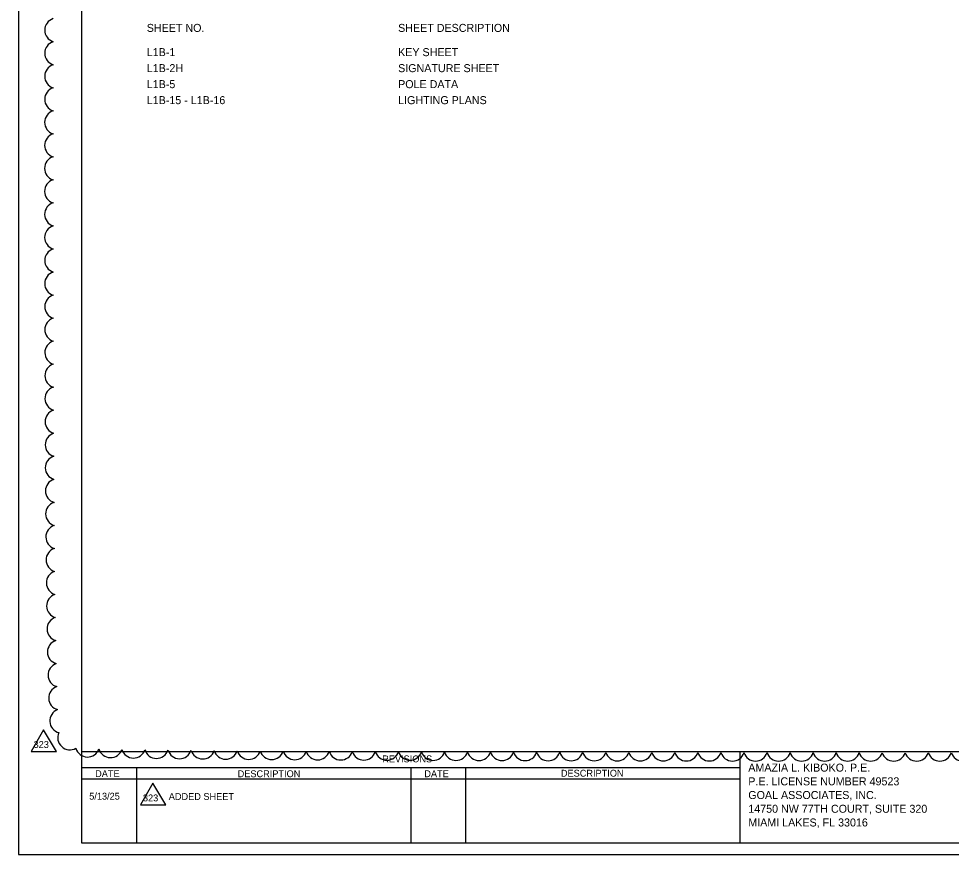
# Model space of a CAD drawing. Extents: x -811.2 to -755.6, y -2295.2 to -2235.1.
# Drawn here: x -783.91 to -775.75, y -2282.95 to -2275.63 of the extents above; entities that cross this region are included whole.
import ezdxf

# ---------------------------------------------------------------- set-up
doc = ezdxf.new("R2010")
doc.units = 0
for name, color, linetype in [('Cloud_dp', 7, 'Continuous'), ('PlotBorder_dp', 7, 'Continuous'), ('SheetBorder_dp', 7, 'Continuous'), ('SheetLines_dp', 7, 'Continuous'), ('TextMinor', 7, 'Continuous'), ('TextMisc', 7, 'Continuous'), ('TextNotes', 7, 'Continuous'), ('TextTitle', 7, 'Continuous')]:
    doc.layers.add(name, color=color, linetype=linetype)

msp = doc.modelspace()

# ---------------------------------------------------------------- linework, layer by layer
at = {"layer": 'Cloud_dp'}
for points in [[(-783.6889, -2281.8566), (-783.7966, -2282.0447), (-783.576, -2282.0447)], [(-782.7321, -2282.3241), (-782.8398, -2282.5122), (-782.6192, -2282.5122)]]:
    msp.add_lwpolyline(points, close=True, dxfattribs=at)
for centre, start, end in [((-783.5726, -2275.7344), 107.45847, 252.45847), ((-783.5727, -2275.9359), 107.46563, 252.46563), ((-783.5728, -2276.1375), 107.47218, 252.47218), ((-783.5729, -2276.339), 107.47822, 252.47822), ((-783.573, -2276.5406), 107.4838, 252.4838), ((-783.573, -2276.7421), 107.48899, 252.48899), ((-783.5731, -2276.9436), 107.49382, 252.49382), ((-783.5731, -2277.1452), 107.49843, 252.49843), ((-783.573, -2277.3467), 107.51148, 252.51148), ((-783.573, -2277.5483), 107.53101, 252.53101), ((-783.5728, -2277.7498), 107.55191, 252.55191), ((-783.5726, -2277.9513), 107.57435, 252.57435), ((-783.5723, -2278.1529), 107.59852, 252.59852), ((-783.5719, -2278.3544), 107.62468, 252.62468), ((-783.5714, -2278.5559), 107.65309, 252.65309), ((-783.5708, -2278.7575), 107.68411, 252.68411), ((-783.5701, -2278.959), 107.71817, 252.71817), ((-783.5693, -2279.1605), 107.75578, 252.75578), ((-783.5683, -2279.3621), 107.79762, 252.79762), ((-783.5672, -2279.5636), 107.84454, 252.84454), ((-783.5659, -2279.7651), 107.89767, 252.89767), ((-783.5644, -2279.9666), 107.95851, 252.95851), ((-783.5626, -2280.1681), 108.02912, 253.02912), ((-783.5606, -2280.3696), 108.11243, 253.11243), ((-783.5583, -2280.5711), 108.21279, 253.21279), ((-783.5556, -2280.7725), 108.33694, 253.33694), ((-783.5523, -2280.974), 108.49611, 253.49611), ((-783.5485, -2281.1754), 108.71068, 253.71068), ((-783.5437, -2281.3767), 109.02298, 254.02298), ((-783.5374, -2281.5778), 109.54201, 254.54201), ((-783.5282, -2281.7785), 110.71007, 255.71007), ((-783.4585, -2281.9255), 155.06518, 300.06518), ((-783.3038, -2281.9884), 195.62937, 340.62937), ((-783.1027, -2281.9939), 196.26473, 341.26473), ((-782.9013, -2281.9977), 196.54985, 341.54985), ((-782.6999, -2282.0008), 196.72204, 341.72204), ((-782.4984, -2282.0033), 196.84059, 341.84059), ((-782.2969, -2282.0055), 196.92865, 341.92865), ((-782.0954, -2282.0073), 196.99739, 341.99739), ((-781.8939, -2282.009), 197.053, 342.053), ((-781.6924, -2282.0105), 197.09919, 342.09919), ((-781.4909, -2282.0118), 197.13834, 342.13834), ((-781.2893, -2282.0131), 197.17209, 342.17209), ((-781.0878, -2282.0142), 197.20158, 342.20158), ((-780.8863, -2282.0152), 197.22762, 342.22762), ((-780.6847, -2282.0161), 197.25085, 342.25085), ((-780.4832, -2282.0169), 197.27174, 342.27174), ((-780.2817, -2282.0177), 197.29065, 342.29065), ((-780.0801, -2282.0184), 197.30788, 342.30788), ((-779.8786, -2282.019), 197.32367, 342.32367), ((-779.6771, -2282.0196), 197.3382, 342.3382), ((-779.4755, -2282.0202), 197.35163, 342.35163), ((-779.274, -2282.0207), 197.3641, 342.3641), ((-779.0724, -2282.0211), 197.37571, 342.37571), ((-778.8709, -2282.0216), 197.38657, 342.38657), ((-778.6693, -2282.0219), 197.39674, 342.39674), ((-778.4678, -2282.0223), 197.40629, 342.40629), ((-778.2663, -2282.0226), 197.4153, 342.4153), ((-778.0647, -2282.0229), 197.4238, 342.4238), ((-777.8632, -2282.0231), 197.43184, 342.43184), ((-777.6616, -2282.0234), 197.43947, 342.43947), ((-777.4601, -2282.0236), 197.44671, 342.44671), ((-777.2585, -2282.0237), 197.4536, 342.4536), ((-777.057, -2282.0239), 197.46017, 342.46017), ((-776.8554, -2282.024), 197.46644, 342.46644), ((-776.6539, -2282.0241), 197.47243, 342.47243), ((-776.4524, -2282.0242), 197.47816, 342.47816), ((-776.2508, -2282.0243), 197.48365, 342.48365), ((-776.0493, -2282.0243), 197.48892, 342.48892), ((-775.8477, -2282.0244), 197.49398, 342.49398), ((-775.6462, -2282.0244), 197.49888, 342.49888)]:
    msp.add_arc(centre, 0.1057, start, end, dxfattribs=at)
at = {"layer": 'PlotBorder_dp'}
msp.add_lwpolyline([(-783.9062, -2282.9457), (-767.4062, -2282.9457), (-767.4062, -2272.3457), (-783.9062, -2272.3457)], close=True, dxfattribs=at)
at = {"layer": 'SheetBorder_dp'}
for p, q in [((-783.3562, -2272.4457), (-783.3562, -2282.8457)), ((-783.3562, -2282.0457), (-767.9562, -2282.0457)), ((-783.3562, -2282.8457), (-767.9562, -2282.8457))]:
    msp.add_line(p, q, dxfattribs=at)
at = {"layer": 'SheetLines_dp'}
for p, q in [((-777.5962, -2282.0457), (-777.5962, -2282.8457)), ((-783.3562, -2282.1857), (-777.5962, -2282.1857)), ((-782.8762, -2282.1857), (-782.8762, -2282.8457)), ((-780.4762, -2282.1857), (-780.4762, -2282.8457)), ((-779.9962, -2282.1857), (-779.9962, -2282.8457)), ((-783.3562, -2282.2857), (-777.5962, -2282.2857))]:
    msp.add_line(p, q, dxfattribs=at)

# ---------------------------------------------------------------- texts
at = {"layer": 'Cloud_dp'}
for p in [(-783.7757, -2282.0146), (-782.8189, -2282.482)]:
    msp.add_text('323', height=0.05998, rotation=0, dxfattribs=at).set_placement(p)
at = {"layer": 'TextMinor'}
for s, p in [('5/13/25', (-783.2889, -2282.4672)), ('ADDED SHEET', (-782.593, -2282.4696))]:
    msp.add_text(s, height=0.06, dxfattribs=at).set_placement(p)
at = {"layer": 'TextMisc'}
msp.add_text('REVISIONS', height=0.06, dxfattribs=at).set_placement((-780.7257, -2282.1406))
for s, rotation, p in [('DATE', 359.86925, (-783.2373, -2282.2697)), ('DESCRIPTION', 0.04975, (-781.9903, -2282.2709)), ('DATE', 359.86925, (-780.3573, -2282.2704)), ('DESCRIPTION', 0.04975, (-779.1626, -2282.266))]:
    msp.add_text(s, height=0.06, rotation=rotation, dxfattribs=at).set_placement(p)
at = {"layer": 'TextNotes'}
for s, p in [('SHEET NO.', (-782.7855, -2275.7495)), ('SHEET DESCRIPTION', (-780.5865, -2275.7495)), ('L1B-1', (-782.7855, -2275.9617)), ('KEY SHEET', (-780.5865, -2275.9617)), ('L1B-2H', (-782.7855, -2276.1017)), ('SIGNATURE SHEET', (-780.5865, -2276.1017)), ('L1B-5', (-782.7855, -2276.2417)), ('POLE DATA', (-780.5865, -2276.2417)), ('L1B-15 - L1B-16', (-782.7855, -2276.3817)), ('LIGHTING PLANS', (-780.5865, -2276.3817))]:
    msp.add_text(s, height=0.07, dxfattribs=at).set_placement(p)
at = {"layer": 'TextTitle'}
for s, p in [('AMAZIA L. KIBOKO. P.E.', (-777.5233, -2282.2218)), ('P.E. LICENSE NUMBER 49523', (-777.5233, -2282.3418)), ('GOAL ASSOCIATES, INC.', (-777.5233, -2282.4618)), ('14750 NW 77TH COURT, SUITE 320', (-777.5233, -2282.5818)), ('MIAMI LAKES, FL 33016', (-777.5233, -2282.7018))]:
    msp.add_text(s, height=0.07, dxfattribs=at).set_placement(p)

doc.saveas('drawing.dxf')
